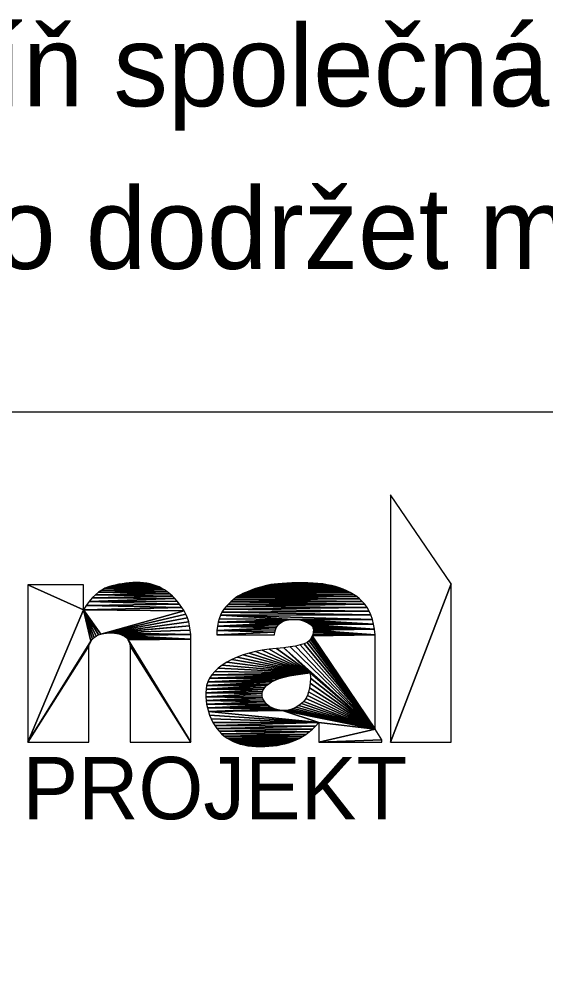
# Model space of a CAD drawing. Extents: x -614134 to -613504, y -1110668 to -1110371.
# Drawn here: x -613656.3 to -613636.9, y -1110630.88 to -1110595.29 of the extents above; entities that cross this region are included whole.
import ezdxf

# ---------------------------------------------------------------- set-up
doc = ezdxf.new("R2010")
doc.units = 0
doc.layers.add('Vrstva 1', color=7, linetype='Continuous')

msp = doc.modelspace()

# ---------------------------------------------------------------- linework, layer by layer
at = {"layer": 'Vrstva 1'}
for points in [[(-613676, -1110609.774), (-613511, -1110609.774), (-613511, -1110662), (-613676, -1110662)], [(-613676, -1110609.774), (-613511, -1110609.774), (-613511, -1110662), (-613676, -1110662)], [(-613642.62, -1110612.842), (-613642.62, -1110621.962), (-613640.38, -1110616.122)], [(-613653.94, -1110617.082), (-613653.94, -1110616.162), (-613655.98, -1110616.162)], [(-613655.98, -1110616.162), (-613655.98, -1110621.962), (-613653.94, -1110617.082)], [(-613653.263, -1110616.348), (-613653.382, -1110616.43), (-613650.847, -1110616.414)], [(-613650.847, -1110616.414), (-613653.382, -1110616.43), (-613650.752, -1110616.488)], [(-613653.142, -1110616.284), (-613653.263, -1110616.348), (-613651.044, -1110616.288)], [(-613651.044, -1110616.288), (-613653.263, -1110616.348), (-613650.944, -1110616.346)], [(-613650.944, -1110616.346), (-613653.263, -1110616.348), (-613650.847, -1110616.414)], [(-613651.146, -1110616.236), (-613653.142, -1110616.284), (-613651.044, -1110616.288)], [(-613653.018, -1110616.236), (-613653.142, -1110616.284), (-613651.146, -1110616.236)], [(-613652.892, -1110616.198), (-613653.018, -1110616.236), (-613651.146, -1110616.236)], [(-613652.766, -1110616.164), (-613652.892, -1110616.198), (-613651.252, -1110616.192)], [(-613651.252, -1110616.192), (-613652.892, -1110616.198), (-613651.146, -1110616.236)], [(-613652.638, -1110616.136), (-613652.766, -1110616.164), (-613651.363, -1110616.154)], [(-613651.363, -1110616.154), (-613652.766, -1110616.164), (-613651.252, -1110616.192)], [(-613652.509, -1110616.114), (-613652.638, -1110616.136), (-613651.478, -1110616.124)], [(-613651.478, -1110616.124), (-613652.638, -1110616.136), (-613651.363, -1110616.154)], [(-613652.379, -1110616.096), (-613652.509, -1110616.114), (-613651.597, -1110616.1)], [(-613651.597, -1110616.1), (-613652.509, -1110616.114), (-613651.478, -1110616.124)], [(-613652.247, -1110616.082), (-613652.379, -1110616.096), (-613651.721, -1110616.084)], [(-613651.721, -1110616.084), (-613652.379, -1110616.096), (-613651.597, -1110616.1)], [(-613652.115, -1110616.074), (-613652.247, -1110616.082), (-613651.721, -1110616.084)], [(-613651.981, -1110616.072), (-613652.115, -1110616.074), (-613651.849, -1110616.074)], [(-613651.849, -1110616.074), (-613652.115, -1110616.074), (-613651.721, -1110616.084)], [(-613647.871, -1110616.398), (-613647.965, -1110616.434), (-613644.1, -1110616.442)], [(-613647.779, -1110616.362), (-613647.871, -1110616.398), (-613644.226, -1110616.376)], [(-613644.226, -1110616.376), (-613647.871, -1110616.398), (-613644.1, -1110616.442)], [(-613647.687, -1110616.328), (-613647.779, -1110616.362), (-613644.226, -1110616.376)], [(-613647.595, -1110616.298), (-613647.687, -1110616.328), (-613644.358, -1110616.318)], [(-613644.358, -1110616.318), (-613647.687, -1110616.328), (-613644.226, -1110616.376)], [(-613647.505, -1110616.268), (-613647.595, -1110616.298), (-613644.358, -1110616.318)], [(-613647.415, -1110616.24), (-613647.505, -1110616.268), (-613644.497, -1110616.266)], [(-613644.497, -1110616.266), (-613647.505, -1110616.268), (-613644.358, -1110616.318)], [(-613647.325, -1110616.214), (-613647.415, -1110616.24), (-613644.642, -1110616.222)], [(-613644.642, -1110616.222), (-613647.415, -1110616.24), (-613644.497, -1110616.266)], [(-613647.237, -1110616.19), (-613647.325, -1110616.214), (-613644.642, -1110616.222)], [(-613647.141, -1110616.168), (-613647.237, -1110616.19), (-613644.794, -1110616.184)], [(-613644.794, -1110616.184), (-613647.237, -1110616.19), (-613644.642, -1110616.222)], [(-613647.03, -1110616.15), (-613647.141, -1110616.168), (-613644.953, -1110616.152)], [(-613644.953, -1110616.152), (-613647.141, -1110616.168), (-613644.794, -1110616.184)], [(-613646.905, -1110616.132), (-613647.03, -1110616.15), (-613644.953, -1110616.152)], [(-613646.766, -1110616.118), (-613646.905, -1110616.132), (-613645.119, -1110616.126)], [(-613645.119, -1110616.126), (-613646.905, -1110616.132), (-613644.953, -1110616.152)], [(-613646.611, -1110616.104), (-613646.766, -1110616.118), (-613645.293, -1110616.106)], [(-613645.293, -1110616.106), (-613646.766, -1110616.118), (-613645.119, -1110616.126)], [(-613646.442, -1110616.094), (-613646.611, -1110616.104), (-613645.293, -1110616.106)], [(-613646.258, -1110616.086), (-613646.442, -1110616.094), (-613645.474, -1110616.09)], [(-613645.474, -1110616.09), (-613646.442, -1110616.094), (-613645.293, -1110616.106)], [(-613646.059, -1110616.08), (-613646.258, -1110616.086), (-613645.661, -1110616.082)], [(-613645.661, -1110616.082), (-613646.258, -1110616.086), (-613645.474, -1110616.09)], [(-613645.857, -1110616.078), (-613646.059, -1110616.08), (-613645.661, -1110616.082)], [(-613640.38, -1110616.122), (-613642.62, -1110621.962), (-613640.38, -1110621.962)], [(-613653.724, -1110616.772), (-613653.833, -1110616.918), (-613650.393, -1110616.872)], [(-613653.612, -1110616.642), (-613653.724, -1110616.772), (-613650.568, -1110616.664)], [(-613650.568, -1110616.664), (-613653.724, -1110616.772), (-613650.479, -1110616.764)], [(-613650.479, -1110616.764), (-613653.724, -1110616.772), (-613650.393, -1110616.872)], [(-613653.498, -1110616.528), (-613653.612, -1110616.642), (-613650.659, -1110616.572)], [(-613650.659, -1110616.572), (-613653.612, -1110616.642), (-613650.568, -1110616.664)], [(-613653.382, -1110616.43), (-613653.498, -1110616.528), (-613650.752, -1110616.488)], [(-613650.752, -1110616.488), (-613653.498, -1110616.528), (-613650.659, -1110616.572)], [(-613648.421, -1110616.712), (-613648.509, -1110616.788), (-613643.658, -1110616.77)], [(-613643.658, -1110616.77), (-613648.509, -1110616.788), (-613643.565, -1110616.874)], [(-613648.332, -1110616.642), (-613648.421, -1110616.712), (-613643.759, -1110616.678)], [(-613643.759, -1110616.678), (-613648.421, -1110616.712), (-613643.658, -1110616.77)], [(-613648.242, -1110616.58), (-613648.332, -1110616.642), (-613643.866, -1110616.592)], [(-613643.866, -1110616.592), (-613648.332, -1110616.642), (-613643.759, -1110616.678)], [(-613648.15, -1110616.524), (-613648.242, -1110616.58), (-613643.866, -1110616.592)], [(-613648.058, -1110616.476), (-613648.15, -1110616.524), (-613643.98, -1110616.514)], [(-613643.98, -1110616.514), (-613648.15, -1110616.524), (-613643.866, -1110616.592)], [(-613647.965, -1110616.434), (-613648.058, -1110616.476), (-613644.1, -1110616.442)], [(-613644.1, -1110616.442), (-613648.058, -1110616.476), (-613643.98, -1110616.514)], [(-613653.94, -1110617.082), (-613655.98, -1110621.962), (-613653.662, -1110618.23)], [(-613653.833, -1110616.918), (-613653.94, -1110617.082), (-613650.308, -1110616.988)], [(-613650.308, -1110616.988), (-613653.94, -1110617.082), (-613650.229, -1110617.112)], [(-613653.94, -1110617.082), (-613653.291, -1110617.976), (-613650.229, -1110617.112)], [(-613653.94, -1110617.082), (-613653.385, -1110618.006), (-613653.291, -1110617.976)], [(-613653.94, -1110617.082), (-613653.469, -1110618.048), (-613653.385, -1110618.006)], [(-613653.94, -1110617.082), (-613653.543, -1110618.098), (-613653.469, -1110618.048)], [(-613653.94, -1110617.082), (-613653.607, -1110618.16), (-613653.543, -1110618.098)], [(-613653.94, -1110617.082), (-613653.662, -1110618.23), (-613653.607, -1110618.16)], [(-613650.393, -1110616.872), (-613653.833, -1110616.918), (-613650.308, -1110616.988)], [(-613650.229, -1110617.112), (-613653.291, -1110617.976), (-613650.161, -1110617.242)], [(-613648.763, -1110617.058), (-613648.832, -1110617.164), (-613643.407, -1110617.124)], [(-613643.407, -1110617.124), (-613648.832, -1110617.164), (-613643.343, -1110617.27)], [(-613648.682, -1110616.96), (-613648.763, -1110617.058), (-613643.481, -1110616.992)], [(-613643.481, -1110616.992), (-613648.763, -1110617.058), (-613643.407, -1110617.124)], [(-613648.596, -1110616.87), (-613648.682, -1110616.96), (-613643.565, -1110616.874)], [(-613643.565, -1110616.874), (-613648.682, -1110616.96), (-613643.481, -1110616.992)], [(-613648.509, -1110616.788), (-613648.596, -1110616.87), (-613643.565, -1110616.874)], [(-613650.161, -1110617.242), (-613653.291, -1110617.976), (-613653.187, -1110617.954)], [(-613650.161, -1110617.242), (-613653.187, -1110617.954), (-613650.104, -1110617.378)], [(-613650.104, -1110617.378), (-613653.187, -1110617.954), (-613650.058, -1110617.522)], [(-613648.938, -1110617.406), (-613648.975, -1110617.54), (-613646.209, -1110617.43)], [(-613646.209, -1110617.43), (-613648.975, -1110617.54), (-613646.291, -1110617.434)], [(-613646.291, -1110617.434), (-613648.975, -1110617.54), (-613646.373, -1110617.446)], [(-613646.373, -1110617.446), (-613648.975, -1110617.54), (-613646.454, -1110617.464)], [(-613646.454, -1110617.464), (-613648.975, -1110617.54), (-613646.535, -1110617.488)], [(-613646.535, -1110617.488), (-613648.975, -1110617.54), (-613646.611, -1110617.52)], [(-613648.89, -1110617.28), (-613648.938, -1110617.406), (-613646.209, -1110617.43)], [(-613648.832, -1110617.164), (-613648.89, -1110617.28), (-613643.343, -1110617.27)], [(-613643.343, -1110617.27), (-613648.89, -1110617.28), (-613643.288, -1110617.432)], [(-613648.89, -1110617.28), (-613646.209, -1110617.43), (-613643.288, -1110617.432)], [(-613646.209, -1110617.43), (-613646.127, -1110617.432), (-613643.288, -1110617.432)], [(-613646.127, -1110617.432), (-613646.044, -1110617.44), (-613643.288, -1110617.432)], [(-613643.288, -1110617.432), (-613646.044, -1110617.44), (-613643.243, -1110617.608)], [(-613646.044, -1110617.44), (-613645.96, -1110617.454), (-613643.243, -1110617.608)], [(-613645.96, -1110617.454), (-613645.876, -1110617.476), (-613643.243, -1110617.608)], [(-613645.876, -1110617.476), (-613645.796, -1110617.502), (-613643.243, -1110617.608)], [(-613650.058, -1110617.522), (-613653.187, -1110617.954), (-613653.081, -1110617.942)], [(-613650.058, -1110617.522), (-613653.081, -1110617.942), (-613650.022, -1110617.672)], [(-613650.022, -1110617.672), (-613653.081, -1110617.942), (-613652.98, -1110617.934)], [(-613650.022, -1110617.672), (-613652.98, -1110617.934), (-613652.885, -1110617.934)], [(-613650.022, -1110617.672), (-613652.885, -1110617.934), (-613649.998, -1110617.83)], [(-613649.998, -1110617.83), (-613652.885, -1110617.934), (-613649.984, -1110617.992)], [(-613649.016, -1110617.84), (-613649.02, -1110618.002), (-613646.885, -1110617.906)], [(-613649.001, -1110617.686), (-613649.016, -1110617.84), (-613646.828, -1110617.74)], [(-613646.828, -1110617.74), (-613649.016, -1110617.84), (-613646.861, -1110617.818)], [(-613646.861, -1110617.818), (-613649.016, -1110617.84), (-613646.885, -1110617.906)], [(-613648.975, -1110617.54), (-613649.001, -1110617.686), (-613646.678, -1110617.562)], [(-613646.678, -1110617.562), (-613649.001, -1110617.686), (-613646.737, -1110617.612)], [(-613646.737, -1110617.612), (-613649.001, -1110617.686), (-613646.787, -1110617.672)], [(-613646.787, -1110617.672), (-613649.001, -1110617.686), (-613646.828, -1110617.74)], [(-613646.611, -1110617.52), (-613648.975, -1110617.54), (-613646.678, -1110617.562)], [(-613645.796, -1110617.502), (-613645.724, -1110617.53), (-613643.243, -1110617.608)], [(-613645.724, -1110617.53), (-613645.662, -1110617.56), (-613643.243, -1110617.608)], [(-613645.662, -1110617.56), (-613645.608, -1110617.592), (-613643.243, -1110617.608)], [(-613645.608, -1110617.592), (-613645.563, -1110617.626), (-613643.243, -1110617.608)], [(-613643.243, -1110617.608), (-613645.563, -1110617.626), (-613643.207, -1110617.798)], [(-613645.563, -1110617.626), (-613645.526, -1110617.662), (-613643.207, -1110617.798)], [(-613645.526, -1110617.662), (-613645.499, -1110617.7), (-613643.207, -1110617.798)], [(-613645.499, -1110617.7), (-613645.48, -1110617.74), (-613643.207, -1110617.798)], [(-613645.48, -1110617.74), (-613645.468, -1110617.784), (-613643.207, -1110617.798)], [(-613645.468, -1110617.784), (-613645.463, -1110617.83), (-613643.207, -1110617.798)], [(-613645.463, -1110617.83), (-613645.464, -1110617.878), (-613643.18, -1110618.002)], [(-613643.207, -1110617.798), (-613645.463, -1110617.83), (-613643.18, -1110618.002)], [(-613652.885, -1110617.934), (-613652.794, -1110617.938), (-613649.984, -1110617.992)], [(-613652.794, -1110617.938), (-613652.709, -1110617.95), (-613649.984, -1110617.992)], [(-613652.709, -1110617.95), (-613652.63, -1110617.968), (-613649.984, -1110617.992)], [(-613652.63, -1110617.968), (-613652.555, -1110617.992), (-613649.984, -1110617.992)], [(-613652.555, -1110617.992), (-613652.486, -1110618.022), (-613649.984, -1110617.992)], [(-613649.984, -1110617.992), (-613652.486, -1110618.022), (-613649.98, -1110618.162)], [(-613652.486, -1110618.022), (-613652.424, -1110618.056), (-613649.98, -1110618.162)], [(-613652.424, -1110618.056), (-613652.37, -1110618.094), (-613649.98, -1110618.162)], [(-613652.37, -1110618.094), (-613652.324, -1110618.136), (-613649.98, -1110618.162)], [(-613652.324, -1110618.136), (-613652.287, -1110618.182), (-613649.98, -1110618.162)], [(-613649.98, -1110618.162), (-613652.287, -1110618.182), (-613649.98, -1110621.962)], [(-613652.287, -1110618.182), (-613652.258, -1110618.232), (-613649.98, -1110621.962)], [(-613646.885, -1110617.906), (-613649.02, -1110618.002), (-613646.9, -1110618.002)], [(-613645.564, -1110618.162), (-613645.615, -1110618.224), (-613643.18, -1110621.482)], [(-613645.532, -1110618.1), (-613645.564, -1110618.162), (-613643.18, -1110621.482)], [(-613645.506, -1110618.04), (-613645.532, -1110618.1), (-613643.18, -1110621.482)], [(-613645.486, -1110617.984), (-613645.506, -1110618.04), (-613643.18, -1110618.002)], [(-613643.18, -1110618.002), (-613645.506, -1110618.04), (-613643.18, -1110621.482)], [(-613645.472, -1110617.93), (-613645.486, -1110617.984), (-613643.18, -1110618.002)], [(-613645.464, -1110617.878), (-613645.472, -1110617.93), (-613643.18, -1110618.002)], [(-613653.662, -1110618.23), (-613655.98, -1110621.962), (-613653.706, -1110618.312)], [(-613653.706, -1110618.312), (-613655.98, -1110621.962), (-613653.74, -1110618.402)], [(-613653.74, -1110618.402), (-613655.98, -1110621.962), (-613653.74, -1110621.962)], [(-613652.258, -1110618.232), (-613652.237, -1110618.284), (-613649.98, -1110621.962)], [(-613652.237, -1110618.284), (-613652.225, -1110618.342), (-613649.98, -1110621.962)], [(-613652.225, -1110618.342), (-613652.22, -1110618.402), (-613649.98, -1110621.962)], [(-613652.22, -1110618.402), (-613652.22, -1110621.962), (-613649.98, -1110621.962)], [(-613647.091, -1110618.532), (-613647.35, -1110618.568), (-613645.576, -1110619.406)], [(-613646.819, -1110618.504), (-613647.091, -1110618.532), (-613645.576, -1110619.406)], [(-613646.556, -1110618.48), (-613646.819, -1110618.504), (-613645.576, -1110619.406)], [(-613646.323, -1110618.45), (-613646.556, -1110618.48), (-613643.18, -1110621.482)], [(-613646.556, -1110618.48), (-613645.576, -1110619.406), (-613643.18, -1110621.482)], [(-613646.121, -1110618.416), (-613646.323, -1110618.45), (-613643.18, -1110621.482)], [(-613645.949, -1110618.376), (-613646.121, -1110618.416), (-613643.18, -1110621.482)], [(-613645.807, -1110618.33), (-613645.949, -1110618.376), (-613643.18, -1110621.482)], [(-613645.696, -1110618.28), (-613645.807, -1110618.33), (-613643.18, -1110621.482)], [(-613645.615, -1110618.224), (-613645.696, -1110618.28), (-613643.18, -1110621.482)], [(-613648.464, -1110618.914), (-613648.65, -1110619.014), (-613645.576, -1110619.406)], [(-613648.266, -1110618.824), (-613648.464, -1110618.914), (-613645.576, -1110619.406)], [(-613648.055, -1110618.744), (-613648.266, -1110618.824), (-613645.576, -1110619.406)], [(-613647.833, -1110618.674), (-613648.055, -1110618.744), (-613645.576, -1110619.406)], [(-613647.598, -1110618.616), (-613647.833, -1110618.674), (-613645.576, -1110619.406)], [(-613647.35, -1110618.568), (-613647.598, -1110618.616), (-613645.576, -1110619.406)], [(-613648.967, -1110619.234), (-613649.095, -1110619.352), (-613645.576, -1110619.406)], [(-613648.819, -1110619.122), (-613648.967, -1110619.234), (-613645.576, -1110619.406)], [(-613648.65, -1110619.014), (-613648.819, -1110619.122), (-613645.576, -1110619.406)], [(-613649.287, -1110619.6), (-613649.352, -1110619.73), (-613646.723, -1110619.616)], [(-613646.723, -1110619.616), (-613649.352, -1110619.73), (-613646.876, -1110619.674)], [(-613646.11, -1110619.474), (-613649.287, -1110619.6), (-613646.339, -1110619.516)], [(-613649.201, -1110619.474), (-613649.287, -1110619.6), (-613646.11, -1110619.474)], [(-613646.339, -1110619.516), (-613649.287, -1110619.6), (-613646.544, -1110619.564)], [(-613646.544, -1110619.564), (-613649.287, -1110619.6), (-613646.723, -1110619.616)], [(-613649.095, -1110619.352), (-613649.201, -1110619.474), (-613645.576, -1110619.406)], [(-613645.576, -1110619.406), (-613649.201, -1110619.474), (-613645.855, -1110619.438)], [(-613645.855, -1110619.438), (-613649.201, -1110619.474), (-613646.11, -1110619.474)], [(-613645.571, -1110619.606), (-613645.58, -1110619.788), (-613643.18, -1110621.482)], [(-613645.576, -1110619.406), (-613645.571, -1110619.606), (-613643.18, -1110621.482)], [(-613649.396, -1110619.866), (-613649.419, -1110620.006), (-613647.191, -1110619.876)], [(-613647.191, -1110619.876), (-613649.419, -1110620.006), (-613647.257, -1110619.948)], [(-613647.257, -1110619.948), (-613649.419, -1110620.006), (-613647.306, -1110620.022)], [(-613649.352, -1110619.73), (-613649.396, -1110619.866), (-613647.005, -1110619.736)], [(-613647.005, -1110619.736), (-613649.396, -1110619.866), (-613647.108, -1110619.804)], [(-613647.108, -1110619.804), (-613649.396, -1110619.866), (-613647.191, -1110619.876)], [(-613646.876, -1110619.674), (-613649.352, -1110619.73), (-613647.005, -1110619.736)], [(-613645.602, -1110619.954), (-613645.636, -1110620.102), (-613643.18, -1110621.482)], [(-613645.58, -1110619.788), (-613645.602, -1110619.954), (-613643.18, -1110621.482)], [(-613649.419, -1110620.006), (-613649.427, -1110620.146), (-613647.306, -1110620.022)], [(-613647.306, -1110620.022), (-613649.427, -1110620.146), (-613647.338, -1110620.096)], [(-613647.338, -1110620.096), (-613649.427, -1110620.146), (-613647.354, -1110620.172)], [(-613649.427, -1110620.146), (-613649.426, -1110620.286), (-613647.354, -1110620.172)], [(-613647.354, -1110620.172), (-613649.426, -1110620.286), (-613647.353, -1110620.248)], [(-613647.353, -1110620.248), (-613649.426, -1110620.286), (-613647.335, -1110620.324)], [(-613649.426, -1110620.286), (-613649.416, -1110620.426), (-613647.335, -1110620.324)], [(-613647.335, -1110620.324), (-613649.416, -1110620.426), (-613647.301, -1110620.402)], [(-613645.684, -1110620.236), (-613645.744, -1110620.354), (-613643.18, -1110621.482)], [(-613645.636, -1110620.102), (-613645.684, -1110620.236), (-613643.18, -1110621.482)], [(-613647.301, -1110620.402), (-613649.416, -1110620.426), (-613647.254, -1110620.476)], [(-613649.416, -1110620.426), (-613649.397, -1110620.564), (-613647.254, -1110620.476)], [(-613647.254, -1110620.476), (-613649.397, -1110620.564), (-613647.199, -1110620.544)], [(-613647.199, -1110620.544), (-613649.397, -1110620.564), (-613647.136, -1110620.602)], [(-613649.397, -1110620.564), (-613649.369, -1110620.7), (-613647.136, -1110620.602)], [(-613647.136, -1110620.602), (-613649.369, -1110620.7), (-613647.065, -1110620.654)], [(-613647.065, -1110620.654), (-613649.369, -1110620.7), (-613646.986, -1110620.698)], [(-613646.093, -1110620.672), (-613646.19, -1110620.718), (-613643.18, -1110621.482)], [(-613645.997, -1110620.612), (-613646.093, -1110620.672), (-613643.18, -1110621.482)], [(-613645.904, -1110620.54), (-613645.997, -1110620.612), (-613643.18, -1110621.482)], [(-613645.818, -1110620.456), (-613645.904, -1110620.54), (-613643.18, -1110621.482)], [(-613645.744, -1110620.354), (-613645.818, -1110620.456), (-613643.18, -1110621.482)], [(-613646.986, -1110620.698), (-613649.369, -1110620.7), (-613646.9, -1110620.734)], [(-613649.369, -1110620.7), (-613649.332, -1110620.836), (-613646.9, -1110620.734)], [(-613646.9, -1110620.734), (-613649.332, -1110620.836), (-613646.805, -1110620.762)], [(-613646.805, -1110620.762), (-613649.332, -1110620.836), (-613646.702, -1110620.782)], [(-613646.702, -1110620.782), (-613649.332, -1110620.836), (-613646.596, -1110620.792)], [(-613646.596, -1110620.792), (-613649.332, -1110620.836), (-613645.26, -1110621.242)], [(-613649.332, -1110620.836), (-613649.286, -1110620.97), (-613645.26, -1110621.242)], [(-613649.286, -1110620.97), (-613649.231, -1110621.104), (-613645.26, -1110621.242)], [(-613646.596, -1110620.792), (-613645.26, -1110621.242), (-613643.18, -1110621.482)], [(-613646.492, -1110620.792), (-613646.596, -1110620.792), (-613643.18, -1110621.482)], [(-613646.389, -1110620.78), (-613646.492, -1110620.792), (-613643.18, -1110621.482)], [(-613646.289, -1110620.754), (-613646.389, -1110620.78), (-613643.18, -1110621.482)], [(-613646.19, -1110620.718), (-613646.289, -1110620.754), (-613643.18, -1110621.482)], [(-613649.231, -1110621.104), (-613649.168, -1110621.232), (-613645.26, -1110621.242)], [(-613649.168, -1110621.232), (-613649.098, -1110621.35), (-613645.26, -1110621.242)], [(-613645.26, -1110621.242), (-613649.098, -1110621.35), (-613645.378, -1110621.366)], [(-613649.098, -1110621.35), (-613649.021, -1110621.462), (-613645.378, -1110621.366)], [(-613645.378, -1110621.366), (-613649.021, -1110621.462), (-613645.496, -1110621.48)], [(-613645.26, -1110621.242), (-613645.26, -1110621.962), (-613643.18, -1110621.482)], [(-613649.021, -1110621.462), (-613648.937, -1110621.562), (-613645.496, -1110621.48)], [(-613645.496, -1110621.48), (-613648.937, -1110621.562), (-613645.617, -1110621.582)], [(-613648.937, -1110621.562), (-613648.847, -1110621.656), (-613645.617, -1110621.582)], [(-613645.617, -1110621.582), (-613648.847, -1110621.656), (-613645.739, -1110621.676)], [(-613648.847, -1110621.656), (-613648.749, -1110621.74), (-613645.739, -1110621.676)], [(-613645.739, -1110621.676), (-613648.749, -1110621.74), (-613645.863, -1110621.758)], [(-613648.749, -1110621.74), (-613648.645, -1110621.814), (-613645.863, -1110621.758)], [(-613645.863, -1110621.758), (-613648.645, -1110621.814), (-613645.988, -1110621.83)], [(-613643.18, -1110621.482), (-613645.26, -1110621.962), (-613642.94, -1110621.882)], [(-613648.645, -1110621.814), (-613648.533, -1110621.88), (-613645.988, -1110621.83)], [(-613645.988, -1110621.83), (-613648.533, -1110621.88), (-613646.115, -1110621.892)], [(-613648.533, -1110621.88), (-613648.415, -1110621.938), (-613646.115, -1110621.892)], [(-613646.115, -1110621.892), (-613648.415, -1110621.938), (-613646.244, -1110621.942)], [(-613648.415, -1110621.938), (-613648.291, -1110621.988), (-613646.244, -1110621.942)], [(-613646.244, -1110621.942), (-613648.291, -1110621.988), (-613646.375, -1110621.986)], [(-613646.375, -1110621.986), (-613648.291, -1110621.988), (-613646.511, -1110622.024)], [(-613648.291, -1110621.988), (-613648.161, -1110622.03), (-613646.511, -1110622.024)], [(-613646.511, -1110622.024), (-613648.161, -1110622.03), (-613646.652, -1110622.054)], [(-613648.161, -1110622.03), (-613648.024, -1110622.064), (-613646.652, -1110622.054)], [(-613646.652, -1110622.054), (-613648.024, -1110622.064), (-613646.796, -1110622.08)], [(-613648.024, -1110622.064), (-613647.882, -1110622.092), (-613646.796, -1110622.08)], [(-613646.796, -1110622.08), (-613647.882, -1110622.092), (-613646.945, -1110622.1)], [(-613647.882, -1110622.092), (-613647.733, -1110622.112), (-613646.945, -1110622.1)], [(-613646.945, -1110622.1), (-613647.733, -1110622.112), (-613647.098, -1110622.114)], [(-613647.733, -1110622.112), (-613647.579, -1110622.122), (-613647.098, -1110622.114)], [(-613647.098, -1110622.114), (-613647.579, -1110622.122), (-613647.256, -1110622.124)], [(-613642.94, -1110621.882), (-613645.26, -1110621.962), (-613642.94, -1110621.962)], [(-613647.579, -1110622.122), (-613647.418, -1110622.126), (-613647.256, -1110622.124)]]:
    msp.add_lwpolyline(points, close=True, dxfattribs=at)

# ---------------------------------------------------------------- texts
for s, p in [('SSP - Skříň společná přístrojová', (-613674.9, -1110598.5)), ('   - Nutno dodržet minimální délku 10m', (-613671.462, -1110604.5))]:
    msp.add_text(s, height=3, dxfattribs=at).set_placement(p)
msp.add_text('PROJEKT', height=2.299, rotation=360, dxfattribs=at).set_placement((-613656.18, -1110624.806))

doc.saveas('drawing.dxf')
